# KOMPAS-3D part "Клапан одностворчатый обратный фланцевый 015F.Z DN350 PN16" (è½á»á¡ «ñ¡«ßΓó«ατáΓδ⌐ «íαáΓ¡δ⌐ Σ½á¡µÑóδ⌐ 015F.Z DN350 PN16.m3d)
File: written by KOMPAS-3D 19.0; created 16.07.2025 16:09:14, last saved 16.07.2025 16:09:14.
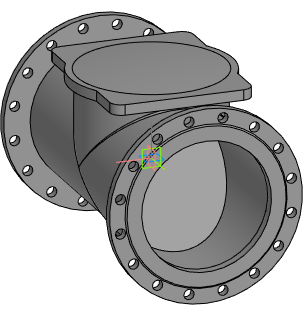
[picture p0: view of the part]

Document properties: Полное имя файла: E:\Dendor Работа Сачек\3D для проектировщиков\5.4 Тип 015F.Z. Клапан одностворчатый обратный фланцевый\stp_Клапан одностворчатый обратный фланцевый 015F.Z PN10_16\Клапан одностворчатый обратный фланцевый 015F.Z DN350 PN16.m3d

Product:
- Part/product: Клапан одностворчатый обратный фланцевый 015F.Z DN350 PN16

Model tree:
1. Операция без истории:1  (labels: Клапан одностворчатый обратный фланцевый 015F.Z DN350 PN16)
2. Операция без истории:2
